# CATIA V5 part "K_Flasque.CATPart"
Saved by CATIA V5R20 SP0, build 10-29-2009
Part number: Flasque
Publications: "epaisseur_flasque", "Arête", "Arête1", "Face", "Face1", "Face2"
Bounding box of the stored display mesh (mm): x -5 to 320, y -255 to 0, z -118 to 60
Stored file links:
  G:\Khaled_CFAO_2011\SIL\SIL_GR2\zthiebault\Khaled\CAD_ThinkMOTION\K_Flasque.CATPart
  F:\Projet Thinkmotion\Catia\FINAL\HabillageFinal.CATProduct
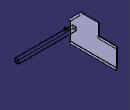
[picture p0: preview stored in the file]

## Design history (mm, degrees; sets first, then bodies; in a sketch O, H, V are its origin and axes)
Parameters
  epaisseur_flasque = 5 mm
  Angle_rail_flasque = 100 deg
Set1
  Point1 "Point_base_flasque4": linked copy from another document
  Point2 "Point_base_flasque5": linked copy from another document
  Point3 "Point_base_flasque6": linked copy from another document
  Point4 "Point_base_flasque7": linked copy from another document
  Point5 "Point_base_flasque1": linked copy from another document
  Point6 "Point_base_flasque2": linked copy from another document
  Point7 "Point_base_flasque3": linked copy from another document
  Line1 "Droite_base_galetdroit": linked copy from another document
  Point8 "Point_base_galet_centrecercle": linked copy from another document
  Point9 "Point_base_galet_centrecercle": linked copy from another document
  Line2 "Droite_base_flasque_lit": linked copy from another document
  Point10 "Point_base_flasque8": linked copy from another document
  Point11 "Point_base_flasque9": linked copy from another document
  Point12 "Point_base_flasque10": linked copy from another document
  Plane1 "Plansymétrieensemble": linked copy from another document
  Plane2 "Plan_base_flasque1": linked copy from another document
  Line3 "Droite_base_flasque_tige": linked copy from another document
  Point13 "Point_base_galet_contact": linked copy from another document
  Point14 "Point_base_galet_contact2": linked copy from another document
Body1 (main body)
  Sketch1 on yz-plane, origin (0, 0, 0), H (0, 1, 0), V (0, 0, 1)
    line L1 (-253.8462, -111) -> (-253.8462, 6.1538)
    point P2 (-253.8462, 6.1538)
    line L2 (-253.8462, 6.1538) -> (-200, 60)
    point P3 (-200, 60)
    line L3 (-200, 60) -> (-100, 60)
    point P4 (-100, 60)
    line L4 (-100, 60) -> (-100, -7)
    line L5 (-100, -7) -> (0, -7)
    point P6 (0, -7)
    line L6 (0, -7) -> (0, -111)
    point P7 (0, -111)
    line L7 (0, -111) -> (-253.8462, -111)
    reference projected point E1 (-100, 60) from Point5
    reference projected point E2 (-200, 60) from Point6
    reference projected point E3 (-253.8462, 6.1538) from Point7
    reference projected point E4 (0, -118) from Point2
    reference projected point E5 (0, 0) from Point3
    reference projected point E6 (0, 0) from Point3
    distance P7 E4 = 7
    distance P6 E5 = 7 {= Sketch1.distance(P7 E4)}
    vertical: L1 V, L4 V, L6 V
    horizontal: L3 H, L5 H, L7 H
    coincidence: P4 E1, P3 E2, P2 E3, E6 L6
  Pad1: profile Sketch1, direction (-1, 0, 0), length 5 {= epaisseur_flasque}
  Sketch2 on face of Pad1 from Sketch1.L6, origin (0, 0, 0), H (-1, 0, 0), V (0, 0, 1)
    line L1 (-2, -104.3218) -> (-2, -116.3218)
    line L2 (-2, -116.3218) -> (0, -118)
    point P3 (0, -118)
    line L3 (0, -118) -> (2, -116.3218)
    line L4 (2, -116.3218) -> (2, -104.3218)
    line L5 (2, -104.3218) -> (-2, -104.3218)
    axis line L6 (-2, -116.3218) -> (2, -116.3218)
    reference intersected line E1 (0, -118) -> (0, 0) from start face of Pad1
    reference projected point E2 (0, -118) from Point13
    angle L2 L3 = 100 {= Angle_rail_flasque}
    length L5 = 4
    distance P3 L1 = 2 {= Sketch2.length(L5) /2}
    length L1 = 12
    vertical: L1 V, L4 V
    horizontal: L5 H
    parallelism: L1 L4, L5 L6
    coincidence: E1 P3, E2 P3
  Pad2: profile Sketch2, direction (0, -1, 0), length 255
  Sketch3 on face of Pad2, origin (0, 0, 0), H (-1, 0, 0), V (0, 0, 1)
    line L1 (-2, -13.6782) -> (-2, -1.6782)
    line L2 (-2, -1.6782) -> (0, 0)
    point P3 (0, 0)
    line L3 (0, 0) -> (2, -1.6782)
    line L4 (2, -1.6782) -> (2, -13.6782)
    line L5 (2, -13.6782) -> (-2, -13.6782)
    axis line L6 (-2, -1.6782) -> (2, -1.6782)
    reference projected point E1 (0, 0) from Point14
    length L5 = 4
    length L4 = 12
    angle L2 L3 = 100 {= Angle_rail_flasque}
    distance P3 L4 = 2 {= Sketch3.length(L5) /2}
    vertical: L1 V, L4 V
    perpendicularity: L4 L5
    parallelism: L6 L5
    coincidence: E1 P3
  Pad3: profile Sketch3, direction (0, -1, 0), length 100
  Sketch4 on start face of Pad1, origin (0, 0, 0), H (0, 1, 0), V (0, 0, 1)
    circle A1 centre (-205.8462, 45) radius 5
    point P1 (-205.8462, 45)
    reference projected point E1 (-205.8462, 45) from Line2
    radius A1 = 5
    coincidence: P1 E1
  Pad4: profile Sketch4, direction (1, 0, 0), length 54
  Sketch5 on start face of Pad1, origin (0, 0, 0), H (0, 1, 0), V (0, 0, 1)
    point P1 (-242.8462, -20)
    line L1 (-242.8462, -20) -> (-222.8462, -20)
    line L2 (-222.8462, -20) -> (-222.8462, -40)
    line L3 (-222.8462, -40) -> (-242.8462, -40)
    line L4 (-242.8462, -40) -> (-242.8462, -20)
    point P2 (-222.8462, -20)
    point P4 (-242.8462, -40)
    reference projected point E1 (-222.8462, -20) from Point10
    reference projected point E2 (-242.8462, -20) from Point11
    reference projected point E3 (-242.8462, -40) from Point12
    line L5 (-241.8462, -21) -> (-223.8462, -21)
    line L6 (-223.8462, -21) -> (-223.8462, -39)
    line L7 (-223.8462, -39) -> (-241.8462, -39)
    line L8 (-241.8462, -39) -> (-241.8462, -21)
    distance L1 L5 = 1
    distance L4 L8 = 1 {= Sketch5.distance(L1 L5)}
    distance L6 L2 = 1 {= Sketch5.distance(L1 L5)}
    distance L7 L3 = 1 {= Sketch5.distance(L1 L5)}
    horizontal: L1 H, L3 H, L5 H, L7 H
    vertical: L2 V, L4 V, L6 V, L8 V
    coincidence: P2 E1, E2 P1, E3 P4
  Pad5: profile Sketch5, direction (1, 0, 0), up to Plane1
  Sketch6 on Plane2, origin (35.5, 0, 0), H (0, -1, 0), V (0, 0, 1)
    line L1 (227.8462, -20) -> (227.8462, -18.0007)
    line L2 (227.8462, -18.0007) -> (250.8462, -18.0007)
    arc A1 centre (250.8462, -20.203) radius 2.2023 from (250.8462, -18.0007) to (252.7534, -21.3042) cw
    point P4 (250.8462, -20.203)
    line L3 (252.7534, -21.3042) -> (244.8462, -35)
    line L4 (244.8462, -35) -> (242.8462, -35)
    line L5 (242.8462, -35) -> (242.8462, -20)
    line L6 (242.8462, -20) -> (227.8462, -20)
    reference projected point E1 (250.8462, -20.203) from Line3
    reference projected point E2 (222.8462, -20) from Point10
    reference projected point E3 (242.8462, -40) from Point12
    length L5 = 15
    angle L3 L5 = 30
    length L6 = 15
    length L4 = 2
    vertical: L1 V, L5 V
    horizontal: L2 H, L4 H, L6 H
    tangency: A1 L2, A1 L3
    coincidence: E1 P4, L6 E2, L5 E3
  Pad6: profile Sketch6, direction (-1, 0, 0), length 1.5, opposite side length 1.5
  Sketch7 on start face of Pad6, origin (37, 0, 0), H (0, 1, 0), V (0, 0, 1)
    circle A1 centre (-250.8462, -20.203) radius 1.5
    point P1 (-250.8462, -20.203)
    reference projected point E1 (-250.8462, -20.203) from Line3
    radius A1 = 1.5
    coincidence: P1 E1
  Pad7: profile Sketch7, direction (1, 0, 0), length 2, opposite side length 5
